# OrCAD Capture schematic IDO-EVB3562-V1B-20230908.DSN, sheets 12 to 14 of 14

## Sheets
12 P24.Audio-HP/1MIC/2SPK: size A3; title: IDO-SBC3566-V1B; note: Audio-HP/1MIC/2SPK
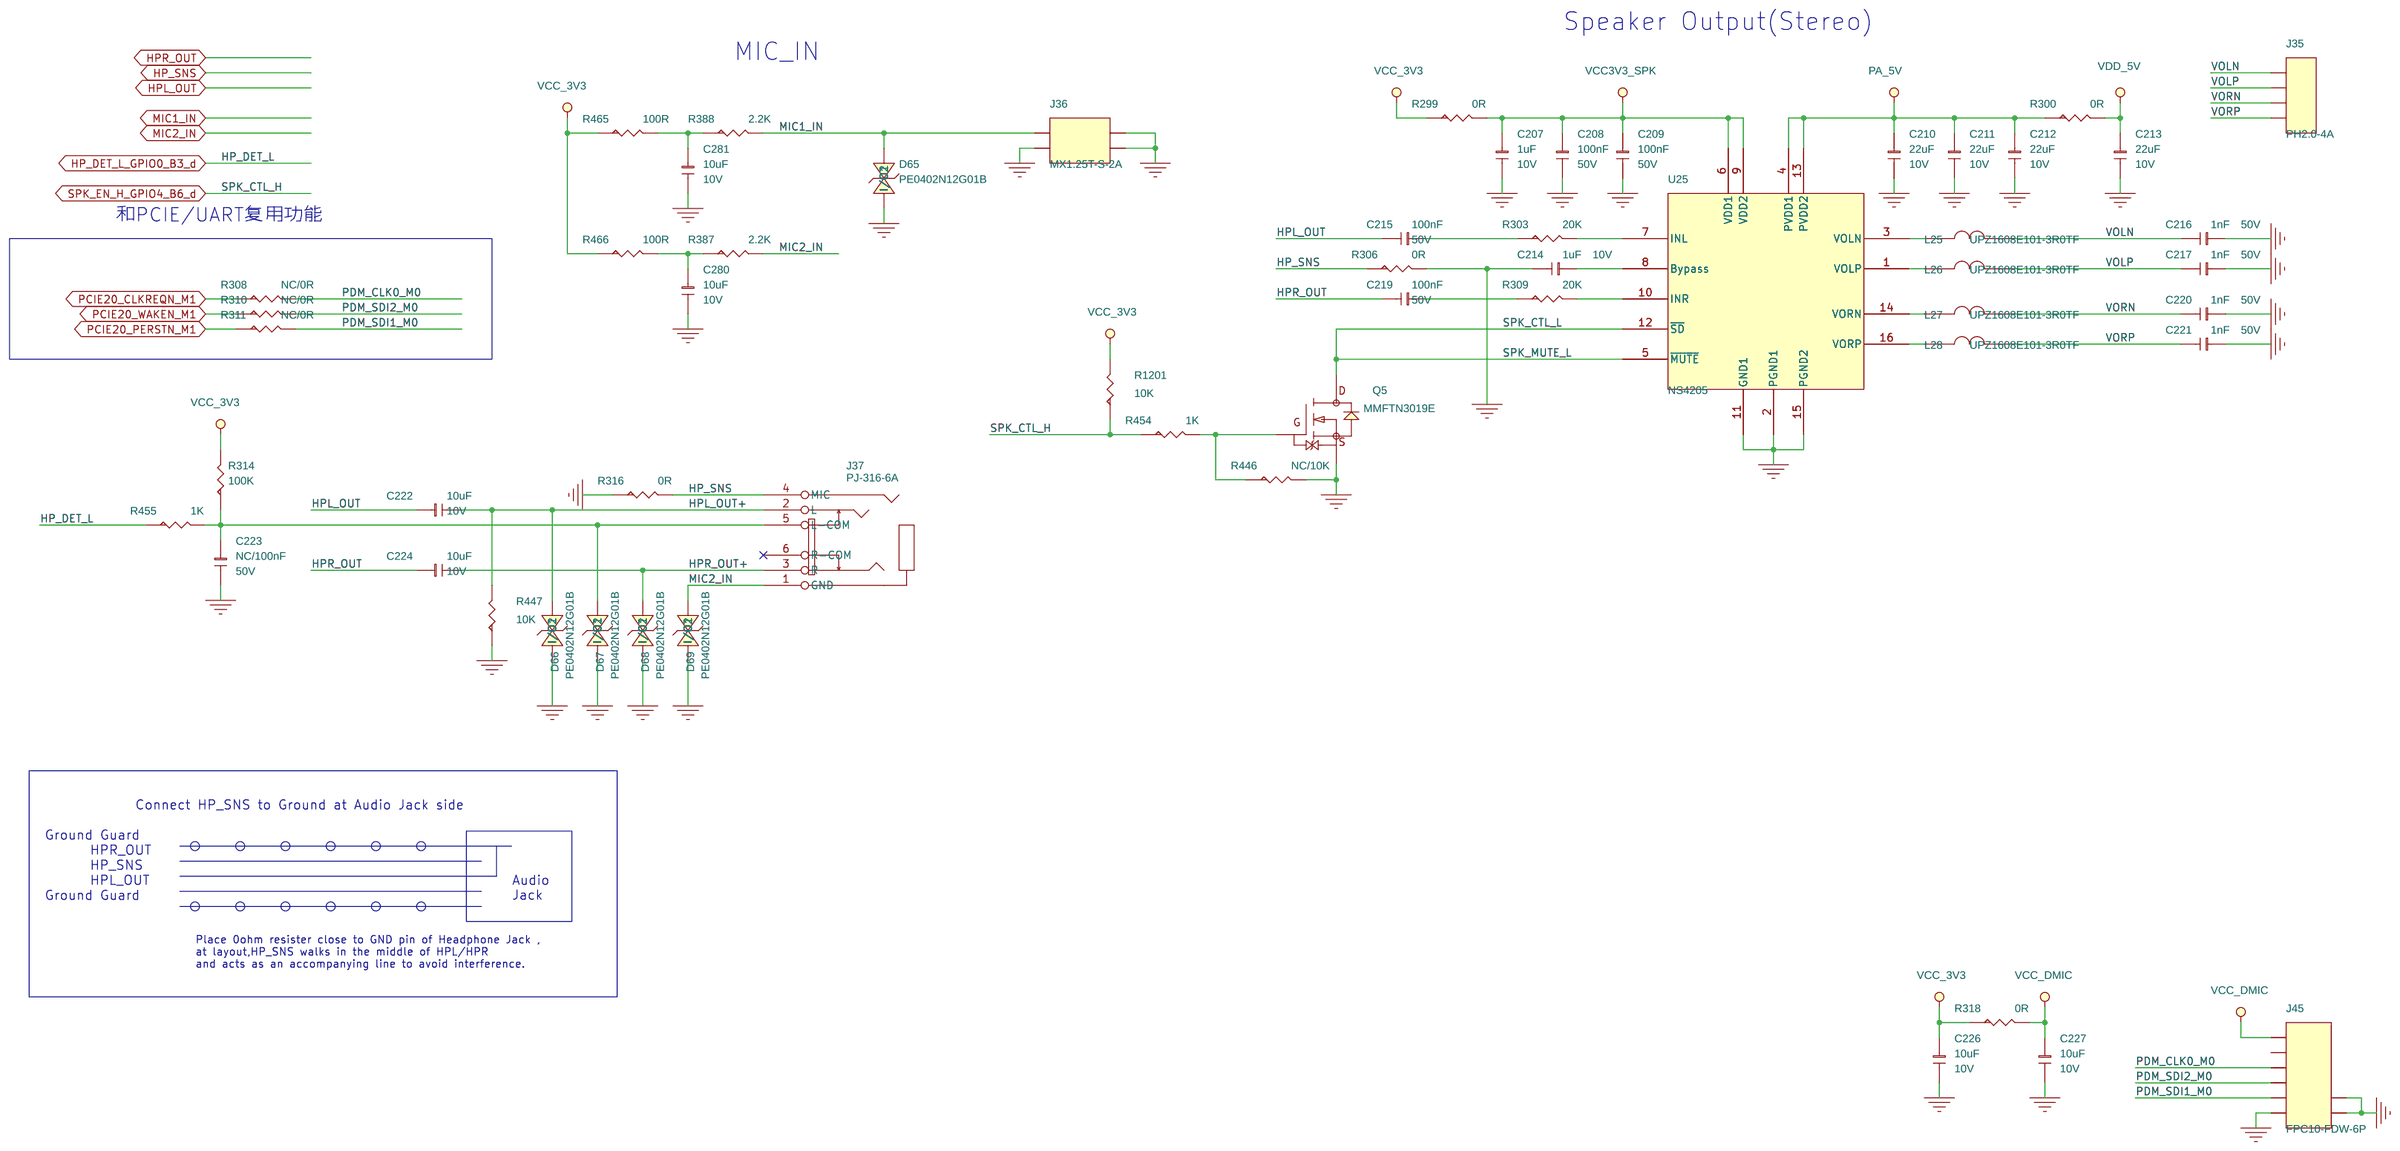
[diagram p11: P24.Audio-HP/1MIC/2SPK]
13 P20. WIFI/BT-SDMMC1_1T1R+UART: size A3; title: IDO-SBC3566-V1B; note: WIFI/BT-SDMMC1_1T1R+UART
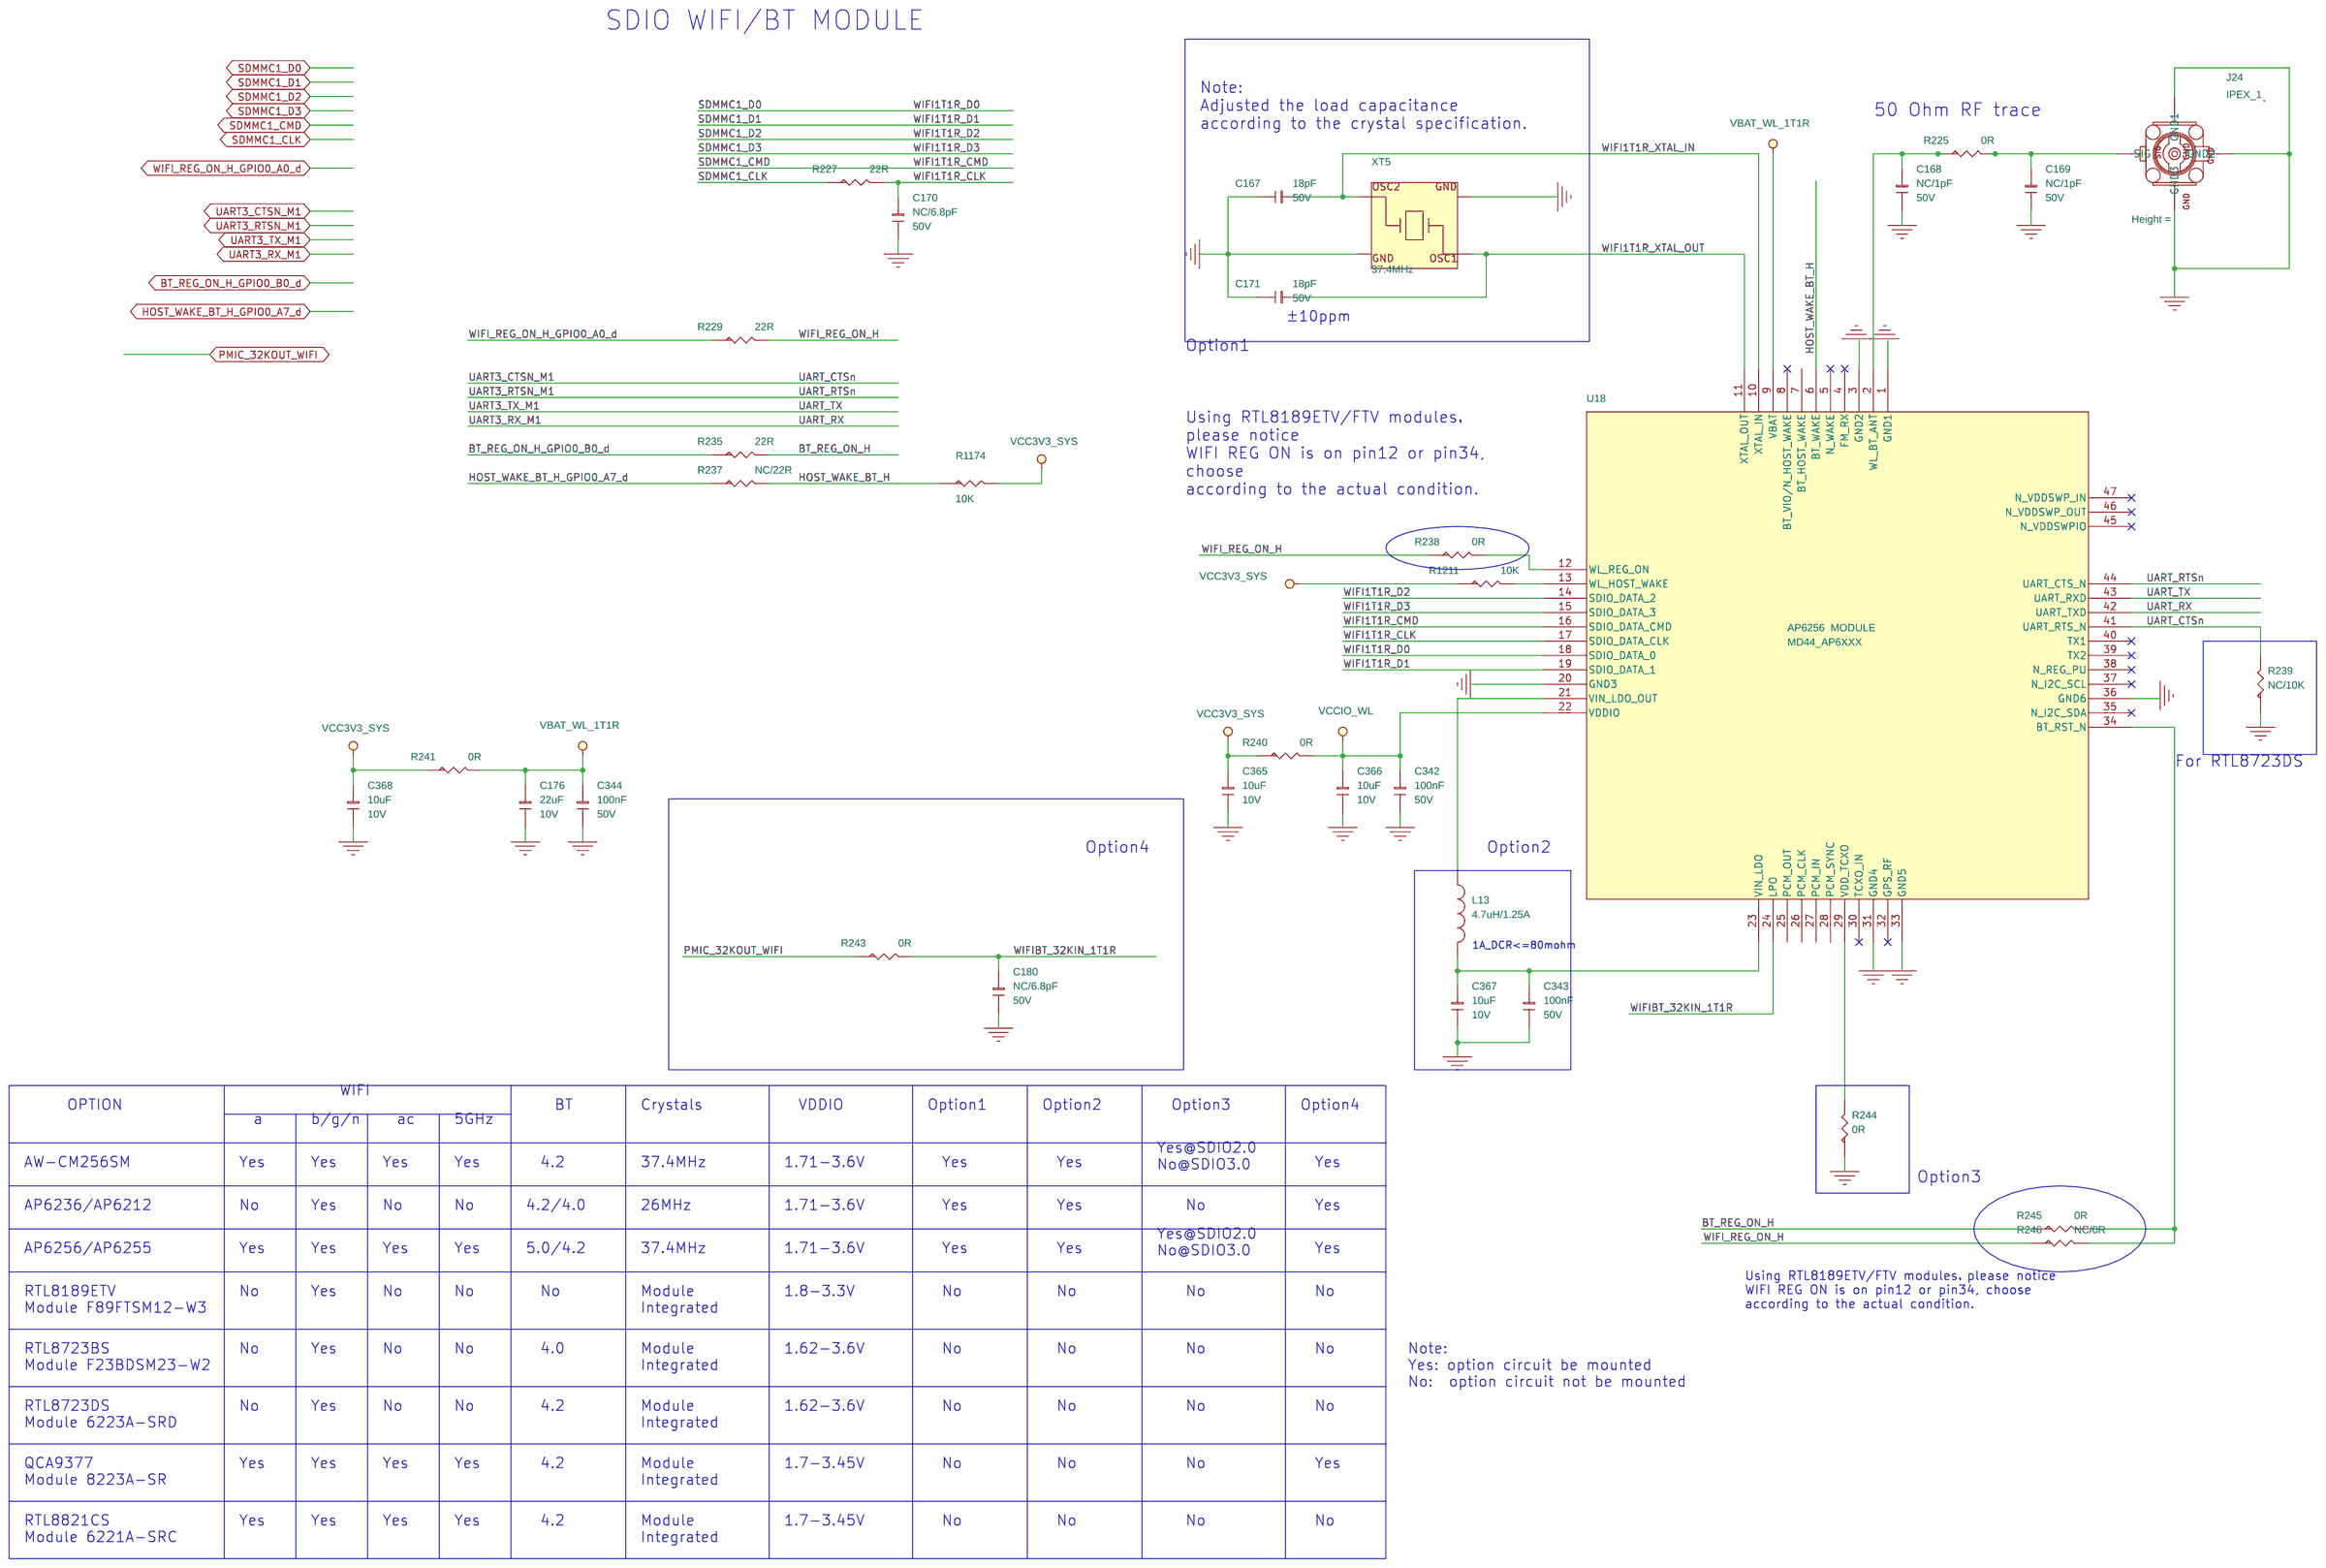
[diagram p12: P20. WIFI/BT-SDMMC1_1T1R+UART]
14 P22.KEY/Debug_UART/RTC/G-senser: size A4; title: IDO-SBC3566-V1B; note: RECOVERY/Reset/PWRON
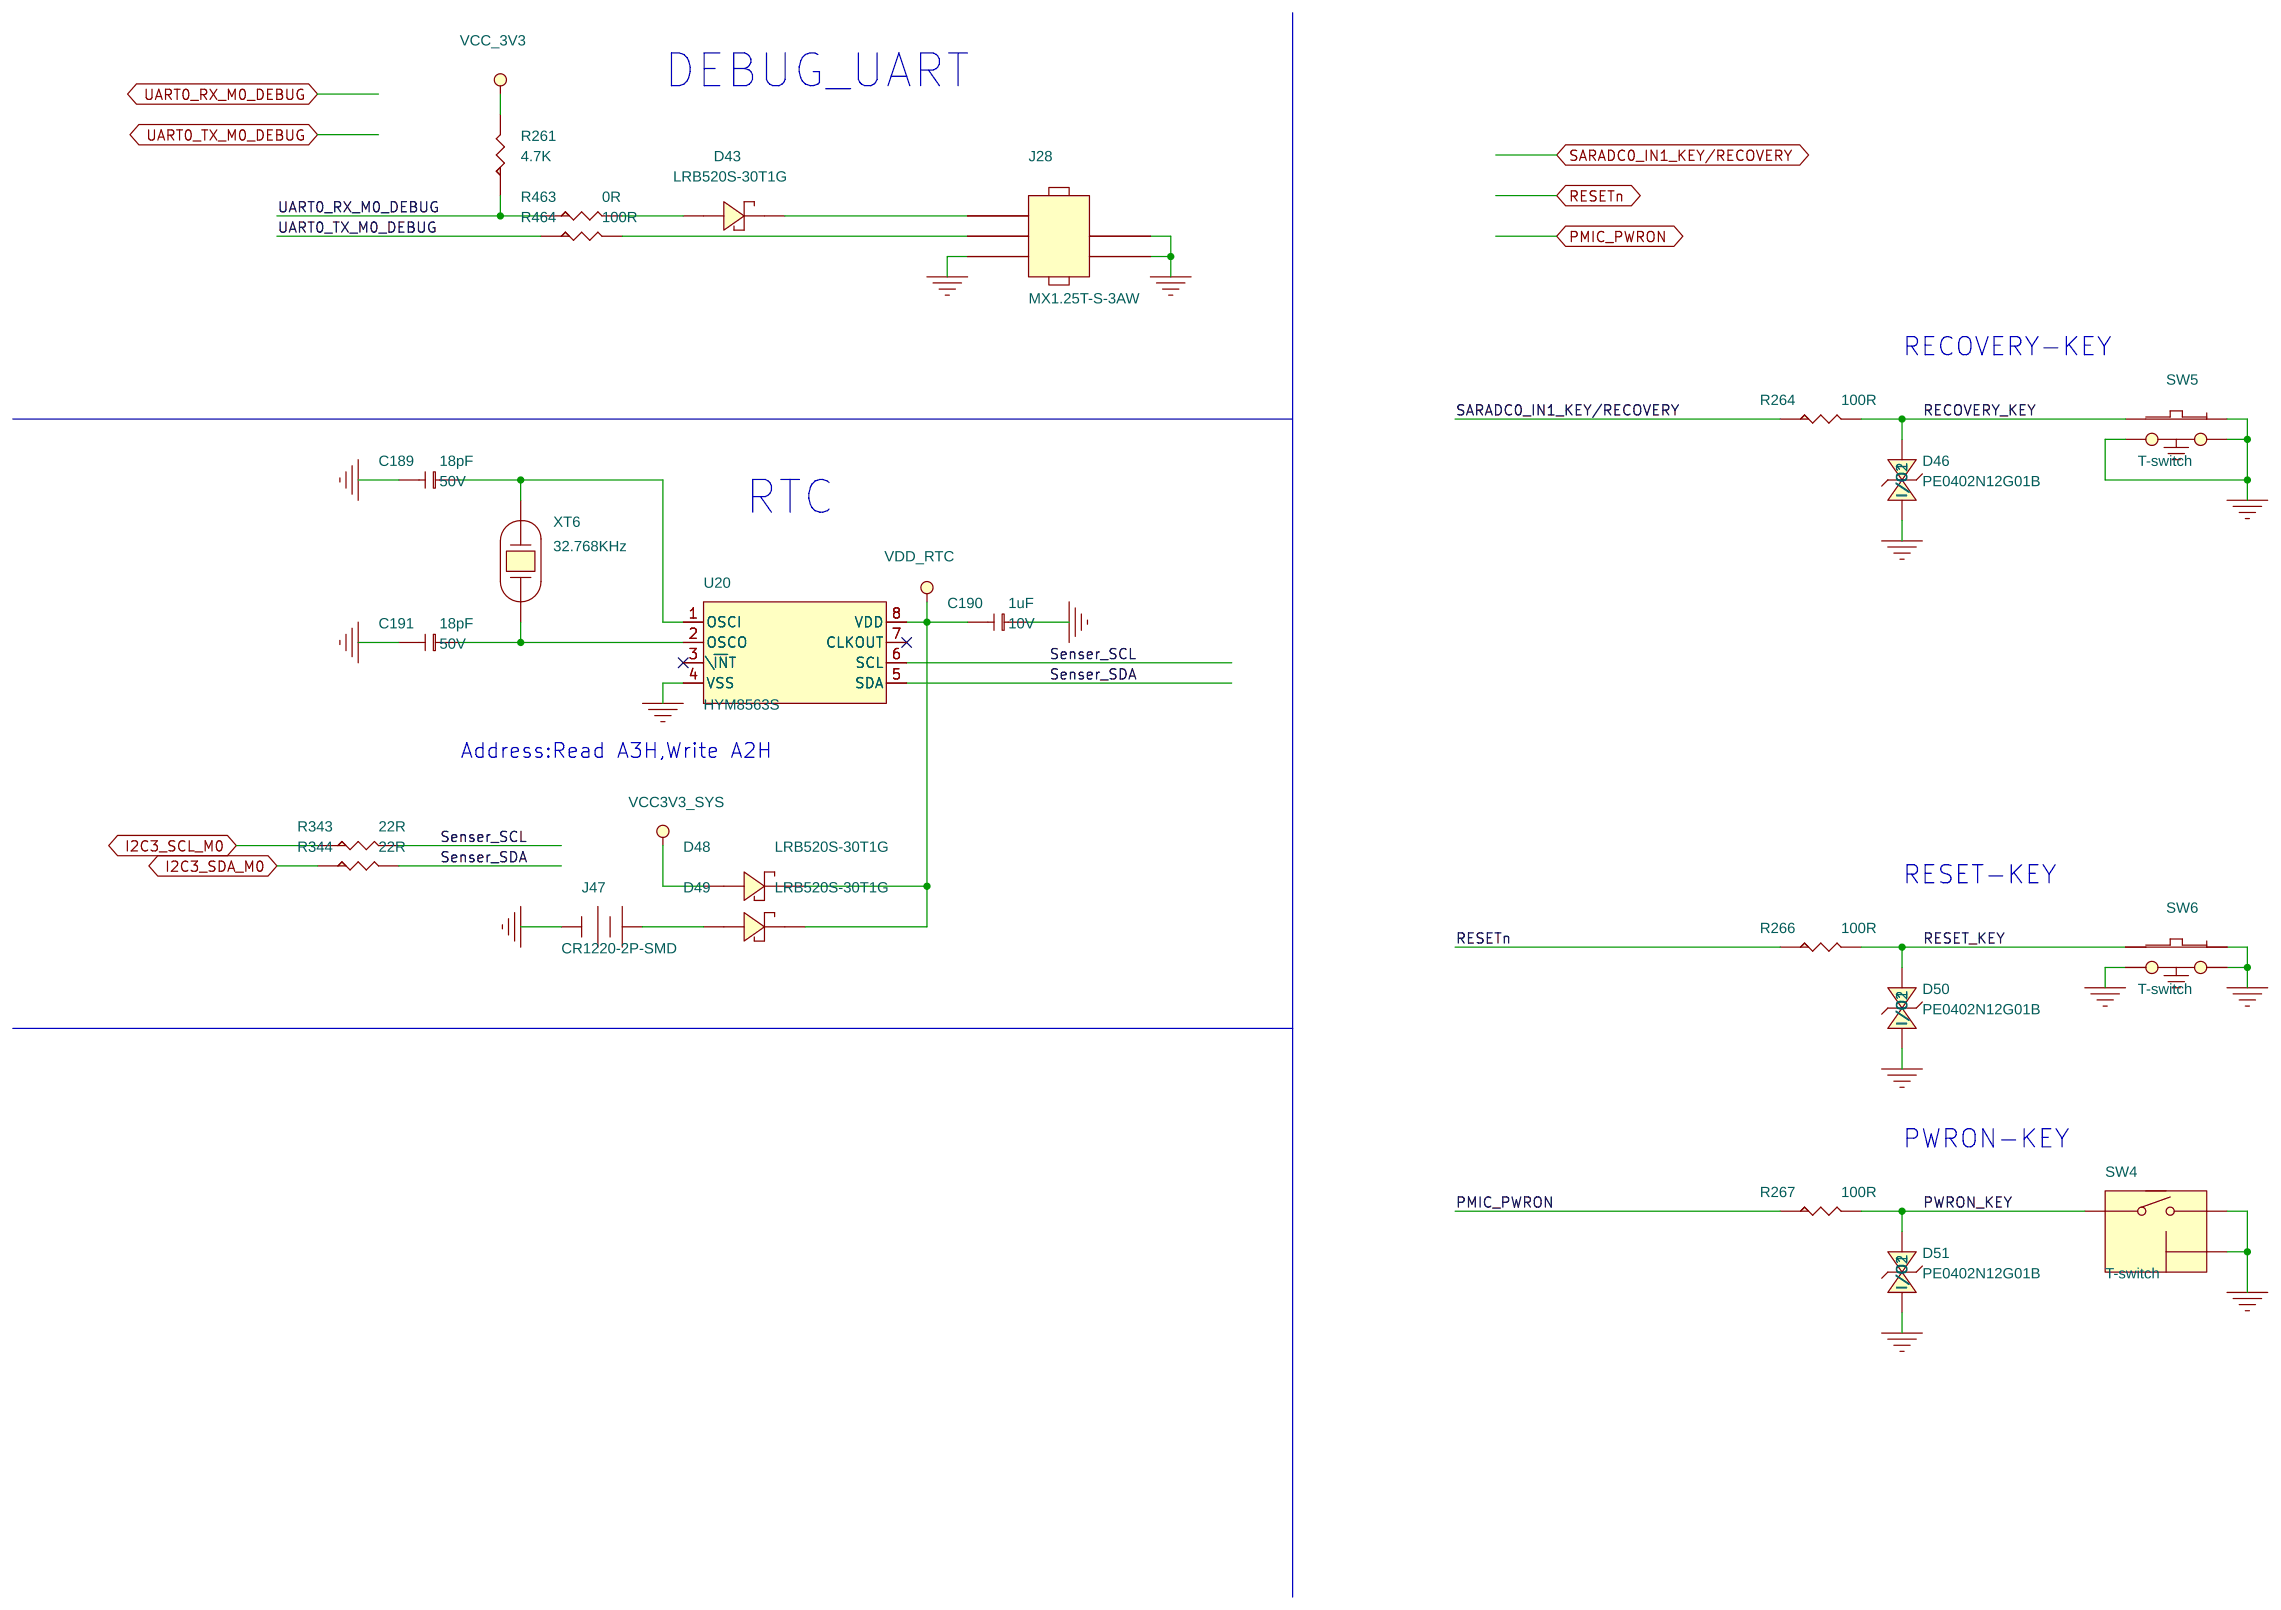
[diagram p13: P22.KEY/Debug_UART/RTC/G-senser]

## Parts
sheet P20. WIFI/BT-SDMMC1_1T1R+UART
C167  18pF  [C0402]
C168  NC/1pF  [C0402]
C169  NC/1pF  [C0402]
C170  NC/6.8pF  [C0402]
C171  18pF  [C0402]
C176  22uF  [C0603]
C180  NC/6.8pF  [C0402]
C342  100nF  [C0402]
C343  100nF  [C0402]
C344  100nF  [C0402]
C365  10uF  [C0603]
C366  10uF  [C0603]
C367  10uF  [C0603]
C368  10uF  [C0603]
J24  IPEX_1  [IPEX-001E]
L13  4.7uH/1.25A  [IND_252012]
R225  0R  [R0402]
R227  22R  [R0402]
R229  22R  [R0402]
R235  22R  [R0402]
R237  NC/22R  [R0402]
R238  0R  [R0402]
R239  NC/10K  [R0402]
R240  0R  [R0603]
R241  0R  [R0603]
R243  0R  [R0402]
R244  0R  [R0402]
R245  0R  [R0402]
R246  NC/0R  [R0402]
R1174  10K  [R0402]
R1211  10K  [R0402]
U18  AP6256  MODULE  [MD44_AP6XXX]
XT5  37.4MHz  [xtal_32x25_4p]
sheet P22.KEY/Debug_UART/RTC/G-senser
C189  18pF  [C0402]
C190  1uF  [C0402]
C191  18pF  [C0402]
D43  LRB520S-30T1G  [SOD523]
D46  PE0402N12G01B  [V0402]
D48  LRB520S-30T1G  [SOD523]
D49  LRB520S-30T1G  [SOD523]
D50  PE0402N12G01B  [V0402]
D51  PE0402N12G01B  [V0402]
J28  MX1.25T-S-3AW  [MX125T-S-3AW]
J47  CR1220-2P-SMD  [CR1220-2P-SMD]
R261  4.7K  [R0402]
R264  100R  [R0402]
R266  100R  [R0402]
R267  100R  [R0402]
R343  22R  [R0402]
R344  22R  [R0402]
R463  0R  [R0402]
R464  100R  [R0402]
SW4  T-switch  [PB-SIDE-P-4_5x4_5]
SW5  T-switch  [PB-SIDE-S-3_5x4_5]
SW6  T-switch  [PB-SIDE-S-3_5x4_5]
U20  HYM8563S  [MSOP-8]
XT6  32.768KHz  [XTAL_32X15_2P]
sheet P24.Audio-HP/1MIC/2SPK
C207  1uF  [C0402]
C208  100nF  [C0402]
C209  100nF  [C0402]
C210  22uF  [C0805]
C211  22uF  [C0805]
C212  22uF  [C0805]
C213  22uF  [C0805]
C214  1uF  [C0402]
C215  100nF  [C0402]
C216  1nF  [C0402]
C217  1nF  [C0402]
C219  100nF  [C0402]
C220  1nF  [C0402]
C221  1nF  [C0402]
C222  10uF  [C0603]
C223  NC/100nF  [C0402]
C224  10uF  [C0603]
C226  10uF  [C0603]
C227  10uF  [C0603]
C280  10uF  [C0603]
C281  10uF  [C0603]
D65  PE0402N12G01B  [V0402]
D66  PE0402N12G01B  [V0402]
D67  PE0402N12G01B  [V0402]
D68  PE0402N12G01B  [V0402]
D69  PE0402N12G01B  [V0402]
J35  PH2.0-4A  [PH200-4A]
J36  MX1.25T-S-2A  [MX125T-S-2A]
J37  PJ-316-6A  [PJ-316A-6A]
J45  FPC10-FDW-6P  [FPC10-6P]
L25  UPZ1608E101-3R0TF  [L0603]
L26  UPZ1608E101-3R0TF  [L0603]
L27  UPZ1608E101-3R0TF  [L0603]
L28  UPZ1608E101-3R0TF  [L0603]
Q5  MMFTN3019E  [SOT523]
R299  0R  [R0603]
R300  0R  [R0603]
R303  20K  [R0402]
R306  0R  [R0402]
R308  NC/0R  [R0402]
R309  20K  [R0402]
R310  NC/0R  [R0402]
R311  NC/0R  [R0402]
R314  100K  [R0402]
R316  0R  [R0402]
R318  0R  [R0603]
R387  2.2K  [R0402]
R388  2.2K  [R0402]
R446  NC/10K  [R0402]
R447  10K  [R0402]
R454  1K  [R0402]
R455  1K  [R0402]
R465  100R  [R0402]
R466  100R  [R0402]
R1201  10K  [R0402]
U25  NS4205  [SOP16-P127-390X990]

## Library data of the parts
C167 C171 C189 C191 = C-0402: DSC1: ±5%; DSC2: 50V; DSC3: C0G; ERP Number: 1010200091; ID: 27; Manufacture: 三星|国巨|村田; Part Name: 贴片电容; Part Number: C020102120027; Price: 0.02
C168 C169 = C-0402: DSC1: ±0.1PF; DSC2: 50V; DSC3: C0G; ID: 11; Manufacture: 三星|国巨|村田; Part Name: 贴片电容; Part Number: C020102120011; Price: 0.02
C170 C180 = C-0402: DSC1: ±0.25PF; DSC2: 50V; DSC3: C0G; ERP Number: 1010200056; ID: 18; Manufacture: 三星|国巨|村田; Part Name: 贴片电容; Part Number: C020102120018; Price: 0.01
C176 = C-0603: DSC1: ±20%; DSC2: 10V; DSC3: X5R; ID: 83; Manufacture: 三星|国巨|村田; Part Name: 贴片电容; Part Number: C020107143899; Price: 0.18
C208 C209 C215 C219 C223 C342-C344 = C-0402: DSC1: ±10%; DSC2: 50V; DSC3: X7R; ERP Number: 1010200128; ID: 61; Manufacture: 三星|国巨|村田; Part Name: 贴片电容; Part Number: C020102120061; Price: 0.05
C222 C224 C226 C227 C280 C281 C365-C368 = C-0603: DSC1: ±20%; DSC2: 10V; DSC3: X5R; ERP Number: 1010200076; ID: 71; Manufacture: 三星|国巨|村田; Part Name: 贴片电容; Part Number: C020102120071; Price: 0.05
J24 = RF-PIEX-1: DSC1: 射频同轴一代IPEX板端贴片天线座子 IPEX/IPX接头 U.FL-R-SMT; DSC2: 贴片; DSC3: U.FL-R-SMT-1(80) 广濑; DSC4: KH-IPEX-K501-29(金航标); ID: 1; Part Name: IPEX座; Part Number: J110103040001
L13 = L-IND: DSC1: ±20%; DSC2: Isat=1.6A; DSC3: Irms=1.25A; DSC4: 260mΩ; DSC5: 2.5*2.0*1.2mm; DSC6: WPN252012H4R7MT(顺络); DSC7: FHD252012S-4R7MT(长江微电); DSC8: ZCRH252012-4.7uH-M(宗成); ID: 54; Manufacture: 宗成|长江微电|顺络; Part Name: 功率电感
R225 R238 R244-R246 = R-0402: DSC1: ±5%; DSC2: 1/16W; ERP Number: 1010200100; ID: 217; Part Name: 贴片电阻; Part Number: C011002080217; Price: 0.01
R227 R229 R235 R237 R343 R344 = R-0402: DSC1: ±5%; DSC2: 1/16W; ERP Number: 1010200173; ID: 262; Part Name: 贴片电阻; Part Number: C011002080262; Price: 0.01
R239 R1174 R1211 = R-0402: DSC1: ±5%; DSC2: 1/16W; ERP Number: 1010200096; ID: 328; Part Name: 贴片电阻; Part Number: C011002080328; Price: 0.01
R240 R241 R299 R300 R318 = R-0603: DSC1: ±1%; DSC2: 1/10W; ERP Number: 1010200158; ID: 1,182; Part Name: 贴片电阻; Part Number: C011002081182; Price: 0.01
R243 R306 R308 R310 R311 R316 R463 = R-0402: DSC1: ±1%; DSC2: 1/16W; ID: 413; Part Name: 贴片电阻; Part Number: C011002080413; Price: 0.01
U18 = MODULE_AP6XXX: WiFi+Bluetooth 4.0(HS)+FM Rx; Created by: JJJ; Manufacturer: Ampak（正基科技）; Manufacturer PN: AP6335; Part Type: module; Priority: A; RK PN: AP6335
XT5 = XTAL-4P: DSC1: 60Ω; DSC2: ±10ppm; DSC3: 12pF; DSC4: -40℃~+85℃; DSC5: 3.2*2.5mm 4P; ID: 13; Manufacture: 爱普生; Part Name: 贴片无源晶振
C190 C207 C214 = C-0402: DSC1: ±10%; DSC2: 10V; DSC3: X5R; ERP Number: 1010200054; ID: 64; Manufacture: 三星|国巨|村田; Part Name: 贴片电容; Part Number: C020102120064; Price: 0.02
D43 D48 D49 = DI-XI-S: DSC1: VR=30V; DSC2: IF=200mA; DSC3: VF=350mV/10mA; DSC4: IR=0.5uA; ID: 2; Manufacture: 乐山无线电; Part Name: 肖特基二级管; Part Number: C040202220002; Price: 0.05; Solder: 推荐
D46 D50 D51 D65-D69 = DI-ESD: DSC1: 双向; DSC2: Vdc=12V; DSC4: Vc=40V; DSC5: Cj=0.05pF; ID: 1; Manufacture: 硕凯; Part Name: ESD; Part Number: C040504013980; Price: 0.06; Solder: 推荐
J28 = J-A-3P: DSC1: 3p; DSC2: 1.25mm间距; DSC3: 卧贴; DSC4: 米黄色胶壳 耐高温; DSC5: JLX-1.25T-3AWB(九龙熹); DSC6: X9821WRS-03-9TSN(星坤); ID: 2; Part Name: MX1.25T; Part Number: J020102800040
J47 = RTC-VBAT-2P: DSC1: CR1220电池适用，贴片，双定位柱; DSC2: 19.3*14.2*4.1mm; DSC3: 贴片; DSC4: JLX-CR1220-2T（九龙熹）; ERP Number: 1040100045; ID: 4; Part Name: 电池座; Part Number: J100303030001
R261 = R-0402: DSC1: ±1%; DSC2: 1/16W; ERP Number: 1010200445; ID: 818; Part Name: 贴片电阻; Part Number: C011002080818; Price: 0.01
R264 R266 R267 R464-R466 = R-0402: DSC1: ±5%; DSC2: 1/16W; ERP Number: 1010200160; ID: 279; Part Name: 贴片电阻; Part Number: C011002080279; Price: 0.01
SW4 = SW-3P: DSC1: 轻触开关 带支架侧键 插件 柄长4.8mm; DSC2: DIP,4.5*4.5mm*4.8mm; DSC3: K2-1109DE-C4SW-01(韩荣); ID: 9; Part Name: 轻触开关; Part Number: C180104013837
SW5 SW6 = SW-TS24CA: DSC1: 轻触开关 侧键 贴片 带定位柱; DSC2: SMD,3.5*4.5mm; DSC3: TS24CA(首韩); ID: 4; Part Name: 轻触开关; Part Number: C180102690004
U20 = U-HYM8563S: DSC1: RTC,I2C, VCC=2.0-5.5V; DSC2: TSSOP8; DSC3: -40℃~+85℃; ID: 16; Manufacture: HAOYU(昊昱); Part Name: RTC芯片; Part Number: C110204273853
XT6 = XTAL-2P: DSC1: 70kΩ; DSC2: ±20ppm; DSC3: 12.5pF; DSC4: -40℃~+85℃; DSC5: 3.2*1.5mm 2P; ID: 2; Manufacture: 泰晶; Part Name: 贴片无源晶振; Part Number: C050102290002; Price: 0.61
C210-C213 = C-0805: DSC1: ±20%; DSC2: 10V; DSC3: X5R; ID: 75; Manufacture: 三星|国巨|村田; Part Name: 贴片电容; Part Number: C020102120075; Price: 0.11
C216 C217 C220 C221 = C-0402: DSC1: ±10%; DSC2: 50V; DSC3: X7R; ERP Number: 1010200084; ID: 54; Manufacture: 三星|国巨|村田; Part Name: 贴片电容; Part Number: C020102120054; Price: 0.01
J35 = J-H-4P: DSC1: 4p; DSC2: 2.0mm间距; DSC3: 通孔180度直针; DSC4: 米黄色胶壳 耐高温; DSC5: JLX-PH20-4A（九龙熹）; DSC6: X2016WV-04-46SN(星坤); ID: 13; Part Name: PH; Part Number: J020302820003
J36 = J-A-2P: DSC1: 2p; DSC2: 1.25mm间距; DSC3: 立贴; DSC4: 米黄色胶壳 耐高温; DSC5: JLX-1.25T-2AB(九龙熹); DSC6: X9821WVS-02-9TSN(星坤); ID: 6; Part Name: MX1.25T; Part Number: J020102800058
J37 = J-PJ-316A-6A: DSC1: 3.5mm贴片式耳机座 凸头 6P 单定位柱; DSC2: 14*6*4mm; DSC4: PJ-316A-6A(韩荣); DSC5: PJ-31160（九龙熹）; ID: 10; Part Name: 音频耳机座; Part Number: J050502940002
J45 = J-FPC-6P: DSC1: 6P; DSC2: 1mm间距; DSC3: 下接 翻盖 卧贴; DSC4: H=2mm; DSC5: 镀锡; DSC6: X10A20L06T（星坤）; ID: 23; Part Name: FPC座; Part Number: J030102870207
L25-L28 = FB-0603: DSC1: 100Ω@100MHz; DSC2: 3A; DSC3: DCR=30mΩ; DSC4: 电源线; ERP Number: 1010200207; ID: 5; Manufacture: 顺络; Part Name: 贴片磁珠; Part Number: C060502370005; Price: 0.03
Q5 = N-MOS-Q: DSC1: Vds=30V; DSC2: Id=100mA; DSC3: Vgs(th)=1.5V; DSC4: Vgs=±20V; DSC5: pd=150mW; ERP Number: 1010800011; ID: 4; Manufacture: 先科; Part Name: N-MOS; Part Number: C030202190004; Price: 0.1
R303 R309 = R-0402: DSC1: ±5%; DSC2: 1/16W; ID: 335; Part Name: 贴片电阻; Part Number: C011002080335; Price: 0.01
R314 = R-0402: DSC1: ±5%; DSC2: 1/16W; ERP Number: 1010200103; ID: 353; Part Name: 贴片电阻; Part Number: C011002080353; Price: 0.01
R387 R388 = R-0402: DSC1: ±1%; DSC2: 1/16W; ID: 778; Part Name: 贴片电阻; Part Number: C011002080778; Price: 0.01
R446 R447 R1201 = R-0402: DSC1: ±1%; DSC2: 1/16W; ERP Number: 1010200140; ID: 856; Part Name: 贴片电阻; Part Number: C011002080856; Price: 0.01
R454 R455 = R-0402: DSC1: ±1%; DSC2: 1/16W; ERP Number: 1010200113; ID: 742; Part Name: 贴片电阻; Part Number: C011002080742; Price: 0.01
U25 = U-NS4205: DSC1: 2*3W @4Ω,3~5.2V，Class D; DSC3: -40~85℃; ERP Number: 1010100190; ID: 2; Manufacture: Nsiway(纳芯威); Part Name: 功放; Part Number: C150102670002; Price: 0.7

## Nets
GND: C167.1 C168.1 C169.1 C170.1 C171.1 C176.1 C180.1 C189.1 C190.2 C191.1 C207.1 C208.1 C209.1 C210.1 C211.1 C212.1 C213.1 C214.1 C216.2 C217.2 C220.2 C221.2 C223.1 C226.1 C227.1 C280.1 C281.1 C342.1 C343.1 C344.1 C365.1 C366.1 C367.1 C368.1 D46.2(I/O1) D50.2(I/O1) D51.2(I/O1) D65.2(I/O1) D66.2(I/O1) D67.2(I/O1) D68.2(I/O1) D69.2(I/O1) J24.1(GND1) J24.3(GND2) J24.4(GND3) J28.3 J28.4 J28.5 J36.2 J36.3 J36.4 J45.6 J45.7 J45.8 J47.2 Q5.2(SOURCE) R239.1 R244.1 R306.2 R316.1 R446.2 R447.1 SW4.2 SW4.3 SW5.1 SW5.2 SW5.3 SW6.1 SW6.2 SW6.3 U18.1(GND1) U18.3(GND2) U18.20(GND3) U18.31(GND4) U18.33(GND5) U18.36(GND6) U20.4(VSS) U25.2(PGND1) U25.11(GND1) U25.15(PGND2) XT5.2 XT5.4 ; also on sheet 1 2 3 4 5 6 7 8 9 10 11
VBAT_WL_1T1R: C176.2 C344.2 R241.2 U18.9(VBAT)
VCC3V3_SPK: C207.2 C208.2 C209.2 R299.2 U25.6(VDD1) U25.9(VDD2)
VCC3V3_SYS: C365.2 C368.2 D48.A R240.1 R241.1 R1174.2 R1211.1 ; also on sheet 1 2 5
VCC_3V3: C226.2 R261.2 R299.1 R314.2 R318.1 R465.1 R466.1 R1201.2 ; also on sheet 1 2 3 5 6 7 8 9 11
VCC_DMIC: C227.2 J45.1 R318.2
VCCIO_WL: C342.2 C366.2 R240.2 U18.22(VDDIO)
VDD_5V: C213.2 R300.2 ; also on sheet 1 5 9
VDD_RTC: C190.1 D48.C D49.C U20.8(VDD)
BT_REG_ON_H: R235.2 R245.1
BT_REG_ON_H_GPIO0_B0_d: R235.1 ; also on sheet 2
HOST_WAKE_BT_H: R237.2 R1174.1 U18.6(BT_WAKE)
HOST_WAKE_BT_H_GPIO0_A7_d: R237.1 ; also on sheet 2
HP_DET_L_GPIO0_B3_d: R455.1 ; also on sheet 2
HP_SNS: J37.4(MIC) R306.1 R316.2 ; also on sheet 2
HPL_OUT: C215.1 C222.2 ; also on sheet 2
HPL_OUT+: C222.1 D66.1(I/O2) J37.2(L) R447.2
HPR_OUT: C219.1 C224.2 ; also on sheet 2
HPR_OUT+: C224.1 D68.1(I/O2) J37.3(R)
I2C3_SCL_M0: R343.1 ; also on sheet 2 5
I2C3_SDA_M0: R344.1 ; also on sheet 2 5
MIC1_IN: D65.1(I/O2) J36.1 R388.2 ; also on sheet 2
MIC2_IN: D69.1(I/O2) J37.1(GND) R387.2 ; also on sheet 2
PA_5V: C210.2 C211.2 C212.2 R300.1 U25.4(PVDD1) U25.13(PVDD2)
PCIE20_CLKREQN_M1: R308.1 ; also on sheet 2 7 10
PCIE20_PERSTN_M1: R311.1 ; also on sheet 2 7 10
PCIE20_WAKEN_M1: R310.1 ; also on sheet 2 7 10
PDM_CLK0_M0: J45.3 R308.2
PDM_SDI1_M0: J45.5 R311.2
PDM_SDI2_M0: J45.4 R310.2
PMIC_32KOUT_WIFI: R243.1 ; also on sheet 2 10
PMIC_PWRON: R267.1 ; also on sheet 2
PWRON_KEY: D51.1(I/O2) R267.2 SW4.1
RECOVERY_KEY: D46.1(I/O2) R264.2 SW5.4
RESET_KEY: D50.1(I/O2) R266.2 SW6.4
RESETn: R266.1 ; also on sheet 2 3
SARADC0_IN1_KEY/RECOVERY: R264.1 ; also on sheet 2
SDMMC1_CLK: R227.1 ; also on sheet 2
SDMMC1_CMD: U18.16(SDIO_DATA_CMD) ; also on sheet 2
SDMMC1_D0: U18.18(SDIO_DATA_0) ; also on sheet 2
SDMMC1_D1: U18.19(SDIO_DATA_1) ; also on sheet 2
SDMMC1_D2: U18.14(SDIO_DATA_2) ; also on sheet 2
SDMMC1_D3: U18.15(SDIO_DATA_3) ; also on sheet 2
Senser_SCL: R343.2 U20.6(SCL)
Senser_SDA: R344.2 U20.5(SDA)
SPK_CTL_L: Q5.3(DRAIN) U25.5(~{MUTE}) U25.12(~{SD})
SPK_EN_H_GPIO4_B6_d: R454.1 R1201.1 ; also on sheet 2
UART0_RX_M0_DEBUG: R261.1 R463.1 ; also on sheet 2
UART0_TX_M0_DEBUG: R464.1 ; also on sheet 2
UART3_CTSN_M1: R239.2 U18.41(UART_RTS_N) ; also on sheet 2
UART3_RTSN_M1: U18.44(UART_CTS_N) ; also on sheet 2
UART3_RX_M1: U18.42(UART_TXD) ; also on sheet 2
UART3_TX_M1: U18.43(UART_RXD) ; also on sheet 2
VOLN: C216.1 J35.1 L25.2
VOLP: C217.1 J35.2 L26.2
VORN: C220.1 J35.3 L27.2
VORP: C221.1 J35.4 L28.2
WIFI1T1R_CLK: C170.2 R227.2 U18.17(SDIO_DATA_CLK)
WIFI1T1R_XTAL_IN: C167.2 U18.10(XTAL_IN) XT5.3
WIFI1T1R_XTAL_OUT: C171.2 U18.11(XTAL_OUT) XT5.1
WIFI_REG_ON_H: R229.2 R238.1 R246.1
WIFI_REG_ON_H_GPIO0_A0_d: R229.1 ; also on sheet 2
WIFIBT_32KIN_1T1R: C180.2 R243.2 U18.24(LPO)
N69774873: R244.2 U18.29(VDD_TCXO)
N69774879: R245.2 R246.2 U18.34(BT_RST_N)
N69774884: C168.2 R225.1 U18.2(WL_BT_ANT)
N69774885: C169.2 J24.2(SIG) R225.2
N69774891: C343.2 C367.2 L13.2 U18.23(VIN_LDO)
N69774914: L13.1 U18.21(VIN_LDO_OUT)
N69774994: R238.2 U18.12(WL_REG_ON)
N69783431: D43.C J28.1
N69783435: J28.2 R464.2
N69783454: D43.A R463.2
N69784782: C189.2 U20.1(OSCI) XT6.1
N69784786: C191.2 U20.2(OSCO) XT6.2
N69784848: D49.A J47.1
N69863607: C281.2 R388.1 R465.2
N69863700: C280.2 R387.1 R466.2
N69865878: C223.2 D67.1(I/O2) J37.5(L-COM) R314.1 R455.2
N69867903: L26.1 U25.1(VOLP)
N69867905: L25.1 U25.3(VOLN)
N69867925: L27.1 U25.14(VORN)
N69867927: L28.1 U25.16(VORP)
N69867929: C215.2 R303.1
N69867931: R303.2 U25.7(INL)
N69867938: C219.2 R309.1
N69867940: R309.2 U25.10(INR)
N69867965: C214.2 U25.8(Bypass)
N69871260: Q5.1(GATE) R446.1 R454.2
N70379039: R1211.2 U18.13(WL_HOST_WAKE)

Not connected (* = marked no-connect by the designer): J37 6(R-COM)*; J45 2; U18 4(FM_RX)* 5(N_WAKE)* 7(BT_HOST_WAKE) 8(BT_VIO/N_HOST_WAKE)* 25(PCM_OUT) 26(PCM_CLK) 27(PCM_IN) 28(PCM_SYNC) 30(TCXO_IN)* 32(GPS_RF)* 35(N_I2C_SDA)* 37(N_I2C_SCL)* 38(N_REG_PU)* 39(TX2)* 40(TX1)* 45(N_VDDSWPIO)* 46(N_VDDSWP_OUT)* 47(N_VDDSWP_IN)*; U20 3(\~{IN}T)* 7(CLKOUT)*

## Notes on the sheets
sheet 12
- Speaker Output(Stereo)
- MIC_IN
- 和PCIE/UART复用功能
- Connect HP_SNS to Ground at Audio Jack side
- Ground Guard
- HPR_OUT
- HP_SNS
- Ground Guard
- HPL_OUT
- Audio
  Jack
- Place 0ohm resister close to GND pin of Headphone Jack ,
  at layout,HP_SNS walks in the middle of HPL/HPR
  and acts as an accompanying line to avoid interference.
sheet 13
- SDIO WIFI/BT MODULE
- Note:
  Adjusted the load capacitance
  according to the crystal specification.
- 50 Ohm RF trace
- ±10ppm
- Option1
- Using RTL8189ETV/FTV modules，
  please notice
  WIFI REG ON is on pin12 or pin34,
  choose
  according to the actual condition.
- For RTL8723DS
- Option4
- Option2
- 1A_DCR<=80mohm
- OPTION
- WIFI
- BT
- Crystals
- VDDIO
- Option1
- Option2
- Option3
- Option4
- a
- b/g/n
- ac
- 5GHz
- Yes@SDIO2.0
  No@SDIO3.0
- AW-CM256SM
- Yes
- Yes
- Yes
- Yes
- 4.2
- 37.4MHz
- 1.71-3.6V
- Yes
- Yes
- Yes
- Option3
- AP6236/AP6212
- No
- Yes
- No
- No
- 4.2/4.0
- 26MHz
- 1.71-3.6V
- Yes
- Yes
- No
- Yes
- Yes@SDIO2.0
  No@SDIO3.0
- AP6256/AP6255
- Yes
- Yes
- Yes
- Yes
- 5.0/4.2
- 37.4MHz
- 1.71-3.6V
- Yes
- Yes
- Yes
- RTL8189ETV
  Module F89FTSM12-W3
- No
- Yes
- No
- No
- No
- Module
  Integrated
- 1.8-3.3V
- No
- No
- No
- No
- Using RTL8189ETV/FTV modules，please notice
  WIFI REG ON is on pin12 or pin34, choose
  according to the actual condition.
- RTL8723BS
  Module F23BDSM23-W2
- No
- Yes
- No
- No
- 4.0
- Module
  Integrated
- 1.62-3.6V
- No
- No
- No
- No
- Note:
  Yes: option circuit be mounted
  No:  option circuit not be mounted
- RTL8723DS
  Module 6223A-SRD
- No
- Yes
- No
- No
- 4.2
- Module
  Integrated
- 1.62-3.6V
- No
- No
- No
- No
- QCA9377
  Module 8223A-SR
- Yes
- Yes
- Yes
- Yes
- 4.2
- Module
  Integrated
- 1.7-3.45V
- No
- No
- No
- Yes
- RTL8821CS
  Module 6221A-SRC
- Yes
- Yes
- Yes
- Yes
- 4.2
- Module
  Integrated
- 1.7-3.45V
- No
- No
- No
- No
sheet 14
- DEBUG_UART
- RECOVERY-KEY
- RTC
- Address:Read A3H,Write A2H
- RESET-KEY
- PWRON-KEY
